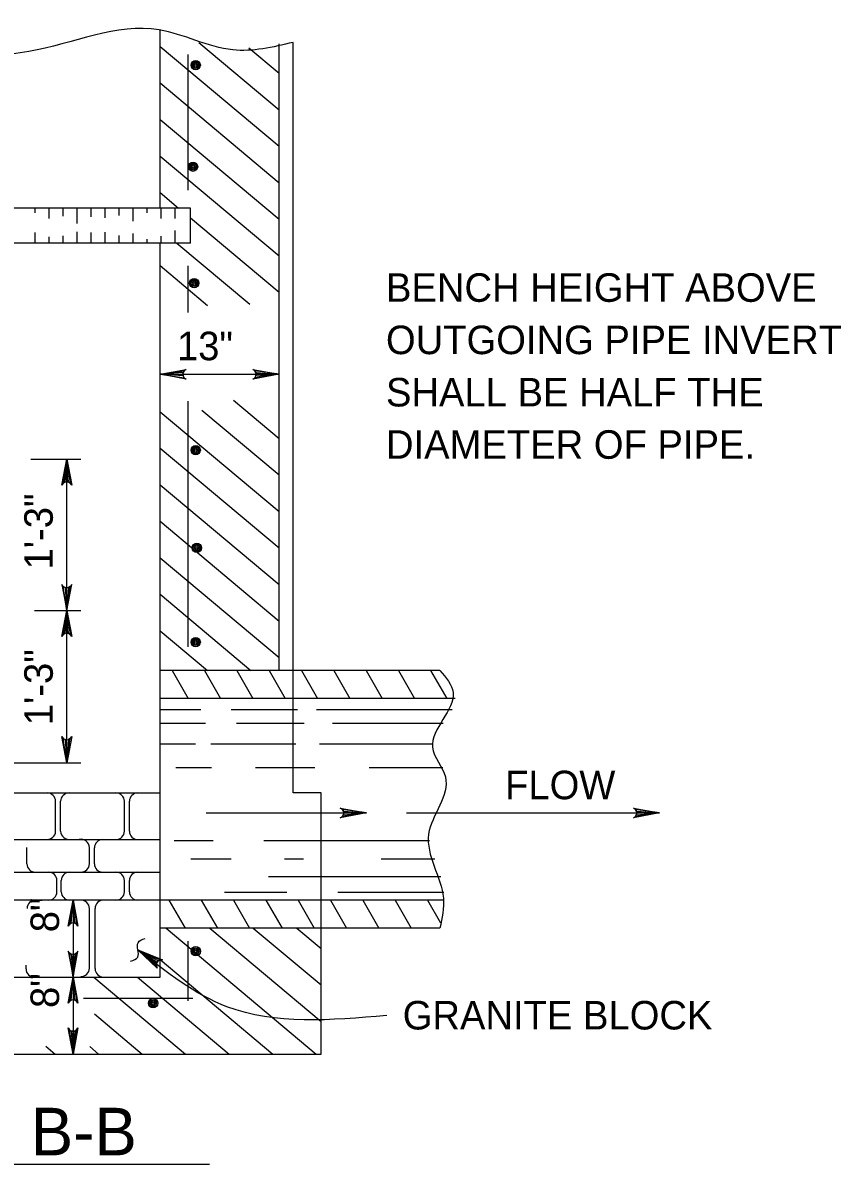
# Model space of a CAD drawing. Extents: x 0.2 to 7.1, y 1.2 to 11.2.
# Drawn here: x 2.099 to 3.819, y 3.123 to 5.523 of the extents above; entities that cross this region are included whole.
import ezdxf

# ---------------------------------------------------------------- set-up
doc = ezdxf.new("R2010")
doc.units = 0
for name, color, linetype in [('DETL-DIMS', 7, 'Continuous'), ('DETL-LINE', 7, 'Continuous'), ('DETL-NOTE', 7, 'Continuous'), ('DETL-PATT', 7, 'Continuous'), ('DETL-TITL', 7, 'Continuous')]:
    doc.layers.add(name, color=color, linetype=linetype)

msp = doc.modelspace()

# ---------------------------------------------------------------- linework, layer by layer
at = {"layer": 'DETL-DIMS'}
for p, q in [((2.3878, 4.7839), (2.6378, 4.7839)), ((2.1161, 4.6055), (2.2211, 4.6055)), ((2.1917, 3.9672), (2.1917, 4.6055)), ((2.1236, 4.2871), (2.2211, 4.2871)), ((2.0041, 3.9672), (2.2211, 3.9672)), ((2.4848, 3.8615), (2.8214, 3.8615)), ((2.9057, 3.8615), (3.4375, 3.8615)), ((2.2049, 3.6782), (2.2049, 3.3547))]:
    msp.add_line(p, q, dxfattribs=at)
for points in [[(2.3878, 4.7839), (2.4426, 4.7942), (2.4384, 4.7913), (2.4362, 4.7876), (2.4356, 4.7839), (2.4362, 4.7803), (2.4384, 4.7766), (2.4426, 4.7737), (2.3878, 4.7839), (2.4384, 4.7766), (2.4362, 4.7803), (2.3878, 4.7839), (2.4356, 4.7839), (2.4362, 4.7876), (2.3878, 4.7839), (2.4384, 4.7913)], [(2.6378, 4.7839), (2.5829, 4.7737), (2.5872, 4.7766), (2.5893, 4.7803), (2.59, 4.7839), (2.5893, 4.7876), (2.5872, 4.7913), (2.5829, 4.7942), (2.6378, 4.7839), (2.5872, 4.7913), (2.5893, 4.7876), (2.6378, 4.7839), (2.59, 4.7839), (2.5893, 4.7803), (2.6378, 4.7839), (2.5872, 4.7766)], [(2.1917, 4.6055), (2.202, 4.5506), (2.199, 4.5549), (2.1954, 4.557), (2.1917, 4.5577), (2.188, 4.557), (2.1843, 4.5549), (2.1814, 4.5506), (2.1917, 4.6055), (2.1843, 4.5549), (2.188, 4.557), (2.1917, 4.6055), (2.1917, 4.5577), (2.1954, 4.557), (2.1917, 4.6055), (2.199, 4.5549)], [(2.1917, 4.2871), (2.202, 4.3419), (2.199, 4.3377), (2.1954, 4.3355), (2.1917, 4.3349), (2.188, 4.3355), (2.1843, 4.3377), (2.1814, 4.3419), (2.1917, 4.2871), (2.1843, 4.3377), (2.188, 4.3355), (2.1917, 4.2871), (2.1917, 4.3349), (2.1954, 4.3355), (2.1917, 4.2871), (2.199, 4.3377)], [(2.1917, 4.2871), (2.202, 4.2323), (2.199, 4.2365), (2.1954, 4.2387), (2.1917, 4.2393), (2.188, 4.2387), (2.1843, 4.2365), (2.1814, 4.2323), (2.1917, 4.2871), (2.1843, 4.2365), (2.188, 4.2387), (2.1917, 4.2871), (2.1917, 4.2393), (2.1954, 4.2387), (2.1917, 4.2871), (2.199, 4.2365)], [(2.1917, 3.9672), (2.1814, 4.0221), (2.1843, 4.0178), (2.188, 4.0157), (2.1917, 4.015), (2.1954, 4.0157), (2.199, 4.0178), (2.202, 4.0221), (2.1917, 3.9672), (2.199, 4.0178), (2.1954, 4.0157), (2.1917, 3.9672), (2.1917, 4.015), (2.188, 4.0157), (2.1917, 3.9672), (2.1843, 4.0178)], [(2.8214, 3.8615), (2.7665, 3.8513), (2.7708, 3.8542), (2.7729, 3.8579), (2.7736, 3.8615), (2.7729, 3.8652), (2.7708, 3.8689), (2.7665, 3.8718), (2.8214, 3.8615), (2.7708, 3.8689), (2.7729, 3.8652), (2.8214, 3.8615), (2.7736, 3.8615), (2.7729, 3.8579), (2.8214, 3.8615), (2.7708, 3.8542)], [(3.4375, 3.8615), (3.3827, 3.8513), (3.3869, 3.8542), (3.3891, 3.8579), (3.3897, 3.8615), (3.3891, 3.8652), (3.3869, 3.8689), (3.3827, 3.8718), (3.4375, 3.8615), (3.3869, 3.8689), (3.3891, 3.8652), (3.4375, 3.8615), (3.3897, 3.8615), (3.3891, 3.8579), (3.4375, 3.8615), (3.3869, 3.8542)], [(2.2049, 3.6782), (2.2152, 3.6234), (2.2123, 3.6276), (2.2086, 3.6298), (2.2049, 3.6304), (2.2012, 3.6298), (2.1976, 3.6276), (2.1946, 3.6234), (2.2049, 3.6782), (2.1976, 3.6276), (2.2012, 3.6298), (2.2049, 3.6782), (2.2049, 3.6304), (2.2086, 3.6298), (2.2049, 3.6782), (2.2123, 3.6276)], [(2.2049, 3.5165), (2.2152, 3.5713), (2.2123, 3.5671), (2.2086, 3.5649), (2.2049, 3.5643), (2.2012, 3.5649), (2.1976, 3.5671), (2.1946, 3.5713), (2.2049, 3.5165), (2.1976, 3.5671), (2.2012, 3.5649), (2.2049, 3.5165), (2.2049, 3.5643), (2.2086, 3.5649), (2.2049, 3.5165), (2.2123, 3.5671)], [(2.3412, 3.5735), (2.3929, 3.5527), (2.3878, 3.5525), (2.384, 3.5505), (2.3815, 3.5478), (2.38, 3.5443), (2.3799, 3.5401), (2.3819, 3.5353), (2.3412, 3.5735), (2.3799, 3.5401), (2.38, 3.5443), (2.3412, 3.5735), (2.3815, 3.5478), (2.384, 3.5505), (2.3412, 3.5735), (2.3878, 3.5525)], [(2.2049, 3.5165), (2.2152, 3.4616), (2.2123, 3.4659), (2.2086, 3.468), (2.2049, 3.4687), (2.2012, 3.468), (2.1976, 3.4659), (2.1946, 3.4616), (2.2049, 3.5165), (2.1976, 3.4659), (2.2012, 3.468), (2.2049, 3.5165), (2.2049, 3.4687), (2.2086, 3.468), (2.2049, 3.5165), (2.2123, 3.4659)], [(2.2049, 3.3547), (2.1946, 3.4095), (2.1976, 3.4053), (2.2012, 3.4031), (2.2049, 3.4025), (2.2086, 3.4031), (2.2123, 3.4053), (2.2152, 3.4095), (2.2049, 3.3547), (2.2123, 3.4053), (2.2086, 3.4031), (2.2049, 3.3547), (2.2049, 3.4025), (2.2012, 3.4031), (2.2049, 3.3547), (2.1976, 3.4053)]]:
    msp.add_lwpolyline(points, dxfattribs=at)
for points in [[(2.3253, 3.5496), (2.341, 3.5585), (2.3414, 3.5887), (2.3562, 3.5978)], [(2.864, 3.4358), (2.5283, 3.4541), (2.3412, 3.5735)]]:
    msp.add_spline(points, degree=3, dxfattribs=at)
at = {"layer": 'DETL-LINE'}
for p, q in [((2.3878, 5.1333), (2.3878, 5.5079)), ((2.6378, 4.1611), (2.6378, 5.4784)), ((2.6672, 4.1611), (2.6672, 5.4817)), ((2.4466, 5.1708), (2.4466, 5.4563)), ((2.4515, 5.1333), (1.9564, 5.1333)), ((2.4515, 5.0598), (2.4515, 5.1333)), ((2.4515, 5.0598), (1.9564, 5.0598)), ((2.3878, 3.5165), (2.3878, 5.0598)), ((2.4466, 4.9135), (2.4466, 5.0116)), ((2.4466, 4.211), (2.4466, 4.7274)), ((2.976, 4.1611), (2.3878, 4.1611)), ((2.6672, 3.9037), (2.6672, 4.1611)), ((3.0077, 4.1022), (2.3878, 4.1022)), ((1.525, 3.9037), (2.3878, 3.9037)), ((2.726, 3.9037), (2.6672, 3.9037)), ((2.726, 3.6194), (2.726, 3.9037)), ((2.1682, 3.8233), (2.1682, 3.8861)), ((2.1787, 3.8233), (2.1787, 3.8861)), ((2.3128, 3.8233), (2.3128, 3.8861)), ((2.3233, 3.8233), (2.3233, 3.8861)), ((1.8815, 3.8057), (2.3548, 3.8057)), ((2.2763, 3.8057), (2.2835, 3.8057)), ((2.3482, 3.8057), (2.3878, 3.8057)), ((2.1078, 3.7547), (2.1078, 3.7888)), ((2.2392, 3.7547), (2.2392, 3.7888)), ((2.2497, 3.7547), (2.2497, 3.788)), ((1.8836, 3.7371), (2.3878, 3.7371)), ((2.1325, 3.7371), (2.1397, 3.7371)), ((2.2044, 3.7371), (2.2116, 3.7371)), ((2.2763, 3.7371), (2.2835, 3.7371)), ((2.3482, 3.7371), (2.3878, 3.7371)), ((2.1709, 3.6959), (2.1709, 3.7194)), ((2.1801, 3.6959), (2.1801, 3.7194)), ((2.3128, 3.6959), (2.3128, 3.7194)), ((2.3233, 3.6959), (2.3233, 3.7194)), ((2.3878, 3.6782), (1.8857, 3.6782)), ((2.1325, 3.6782), (2.1397, 3.6782)), ((2.9828, 3.6782), (2.3878, 3.6782)), ((2.2392, 3.5351), (2.2392, 3.6606)), ((2.251, 3.5342), (2.251, 3.6606)), ((2.976, 3.6194), (2.3878, 3.6194)), ((2.726, 3.3547), (2.726, 3.6194)), ((2.4466, 3.4662), (2.4466, 3.5922)), ((2.106, 3.534), (2.106, 3.5416)), ((1.525, 3.5165), (2.3878, 3.5165)), ((2.2269, 3.4723), (2.4563, 3.4723)), ((1.1868, 3.3547), (2.726, 3.3547))]:
    msp.add_line(p, q, dxfattribs=at)
for centre, radius in [((2.4626, 5.434), 0.0098), ((2.4626, 5.434), 0.00735), ((2.4626, 5.434), 0.0049), ((2.4626, 5.434), 0.00245), ((2.457, 5.2203), 0.0098), ((2.457, 5.2203), 0.00735), ((2.457, 5.2203), 0.0049), ((2.457, 5.2203), 0.00245), ((2.4594, 4.9757), 0.0098), ((2.4594, 4.9757), 0.00735), ((2.4594, 4.9757), 0.0049), ((2.4594, 4.9757), 0.00245), ((2.4626, 4.6244), 0.0098), ((2.4626, 4.6244), 0.00735), ((2.4626, 4.6244), 0.0049), ((2.4626, 4.6244), 0.00245), ((2.465, 4.4189), 0.0098), ((2.465, 4.4189), 0.00735), ((2.465, 4.4189), 0.0049), ((2.465, 4.4189), 0.00245), ((2.4626, 4.2209), 0.0098), ((2.4626, 4.2209), 0.00735), ((2.4626, 4.2209), 0.0049), ((2.4626, 4.2209), 0.00245), ((2.4627, 3.5708), 0.0098), ((2.4627, 3.5708), 0.00735), ((2.4627, 3.5708), 0.0049), ((2.4627, 3.5708), 0.00245), ((2.3731, 3.4614), 0.0098), ((2.3731, 3.4614), 0.00735), ((2.3731, 3.4614), 0.0049), ((2.3731, 3.4614), 0.00245)]:
    msp.add_circle(centre, radius, dxfattribs=at)
for centre, start, end in [((2.1506, 3.8861), 0, 90), ((2.1964, 3.8861), 90, 180), ((2.2951, 3.8861), 0, 90), ((2.3409, 3.8861), 90, 180), ((2.1506, 3.8233), 258.2538, 0), ((2.1964, 3.8233), 180, 281.7563), ((2.2951, 3.8233), 270, 0), ((2.3409, 3.8233), 180, 270), ((2.2215, 3.7888), 0, 101.7563), ((2.2673, 3.788), 90, 180), ((2.1255, 3.7547), 180, 270), ((2.2215, 3.7547), 270, 0), ((2.2673, 3.7547), 180, 270), ((2.1532, 3.7194), 0, 90), ((2.1977, 3.7194), 90, 180), ((2.2951, 3.7194), 0, 90), ((2.3409, 3.7194), 90, 180), ((2.1532, 3.6959), 270, 0), ((2.1977, 3.6959), 180, 270), ((2.2951, 3.6959), 270, 0), ((2.3409, 3.6959), 180, 270), ((2.126, 3.6606), 90, 180), ((2.2215, 3.6606), 0, 90), ((2.2687, 3.6606), 90, 180), ((2.1236, 3.534), 180, 270), ((2.2215, 3.5351), 270, 0), ((2.2687, 3.5342), 180, 270)]:
    msp.add_arc(centre, 0.0176, start, end, dxfattribs=at)
for points in [[(2.6672, 5.4817), (2.5405, 5.4658), (2.386, 5.508), (2.112, 5.4623), (1.5326, 5.5185), (1.2456, 5.4817)], [(2.976, 4.1611), (3.0036, 4.115), (2.9603, 3.9997), (2.9874, 3.9373), (2.9521, 3.8167), (2.9833, 3.6825), (2.976, 3.6194)]]:
    msp.add_spline(points, degree=3, dxfattribs=at)
at = {"layer": 'DETL-PATT'}
for p, q in [((2.3878, 5.4731), (2.6378, 5.2633)), ((2.4694, 5.4814), (2.6378, 5.3401)), ((2.5744, 5.4701), (2.6378, 5.4169)), ((2.3878, 5.3963), (2.6378, 5.1866)), ((2.3878, 5.3195), (2.6378, 5.1098)), ((2.3878, 5.2428), (2.6378, 5.033)), ((2.3878, 5.166), (2.4267, 5.1333)), ((2.1247, 5.1333), (2.1247, 5.1233)), ((2.1541, 5.1333), (2.1541, 5.1117)), ((2.1835, 5.1333), (2.1835, 5.1166)), ((2.2129, 5.1333), (2.2129, 5.1011)), ((2.2424, 5.1333), (2.2424, 5.1146)), ((2.2718, 5.1333), (2.2718, 5.1127)), ((2.3012, 5.1333), (2.3012, 5.1175)), ((2.3306, 5.1333), (2.3306, 5.1059)), ((2.36, 5.1333), (2.36, 5.1233)), ((2.3894, 5.1333), (2.3894, 5.1117)), ((2.4188, 5.1333), (2.4188, 5.1117)), ((2.4515, 5.1125), (2.6378, 4.9562)), ((2.1247, 5.0817), (2.1247, 5.0598)), ((2.1541, 5.073), (2.1541, 5.0598)), ((2.1835, 5.0749), (2.1835, 5.0598)), ((2.2129, 5.0836), (2.2129, 5.0598)), ((2.2424, 5.0817), (2.2424, 5.0598)), ((2.2718, 5.0827), (2.2718, 5.0598)), ((2.3012, 5.0759), (2.3012, 5.0598)), ((2.3306, 5.0798), (2.3306, 5.0598)), ((2.36, 5.0681), (2.36, 5.0598)), ((2.3894, 5.074), (2.3894, 5.0598)), ((2.4188, 5.0865), (2.4188, 5.0598)), ((2.4228, 5.0598), (2.5763, 4.931)), ((2.3878, 5.0124), (2.4874, 4.9288)), ((2.5418, 4.7296), (2.6378, 4.649)), ((2.3878, 4.7052), (2.6378, 4.4955)), ((2.4753, 4.7085), (2.6378, 4.5722)), ((2.3878, 4.6284), (2.6378, 4.4187)), ((2.3878, 4.5517), (2.6378, 4.3419)), ((2.3878, 4.4749), (2.6378, 4.2651)), ((2.3878, 4.3981), (2.6378, 4.1883)), ((2.3878, 4.3213), (2.5787, 4.1611)), ((2.3878, 4.2445), (2.4872, 4.1611)), ((2.413, 4.1611), (2.447, 4.1022)), ((2.4809, 4.1611), (2.5149, 4.1022)), ((2.5489, 4.1611), (2.5828, 4.1022)), ((2.6168, 4.1611), (2.6507, 4.1022)), ((2.6847, 4.1611), (2.7187, 4.1022)), ((2.7526, 4.1611), (2.7866, 4.1022)), ((2.8206, 4.1611), (2.8545, 4.1022)), ((2.8885, 4.1611), (2.9224, 4.1022)), ((2.9564, 4.1611), (2.9904, 4.1022)), ((2.4734, 4.0781), (2.3878, 4.0781)), ((2.6765, 4.0781), (2.5373, 4.0781)), ((3.0013, 4.0781), (2.7165, 4.0781)), ((2.483, 4.0493), (2.3878, 4.0493)), ((2.6909, 4.0493), (2.5485, 4.0493)), ((2.9824, 4.0493), (2.7501, 4.0493)), ((2.4622, 4.0061), (2.3878, 4.0061)), ((2.6733, 4.0061), (2.4942, 4.0061)), ((2.9604, 4.0061), (2.7229, 4.0061)), ((2.4958, 3.9565), (2.4206, 3.9565)), ((2.7133, 3.9565), (2.5885, 3.9565)), ((2.9818, 3.9565), (2.8269, 3.9565)), ((2.499, 3.8028), (2.4174, 3.8028)), ((2.9539, 3.8028), (2.6061, 3.8028)), ((2.5373, 3.7644), (2.4526, 3.7644)), ((2.6893, 3.7644), (2.6493, 3.7644)), ((2.9654, 3.7644), (2.8525, 3.7644)), ((2.9781, 3.7276), (2.6157, 3.7276)), ((2.4062, 3.6782), (2.4402, 3.6194)), ((2.4741, 3.6782), (2.5081, 3.6194)), ((2.6541, 3.694), (2.523, 3.694)), ((2.5421, 3.6782), (2.576, 3.6194)), ((2.61, 3.6782), (2.644, 3.6194)), ((2.6779, 3.6782), (2.7119, 3.6194)), ((2.7458, 3.6782), (2.7798, 3.6194)), ((2.9838, 3.694), (2.7613, 3.694)), ((2.8138, 3.6782), (2.8477, 3.6194)), ((2.8817, 3.6782), (2.9157, 3.6194)), ((2.9496, 3.6782), (2.9773, 3.6303)), ((2.4006, 3.6194), (2.7161, 3.3547)), ((2.4921, 3.6194), (2.726, 3.4232)), ((2.5837, 3.6194), (2.726, 3.5)), ((2.6752, 3.6194), (2.726, 3.5767)), ((2.3878, 3.5534), (2.6246, 3.3547)), ((2.2488, 3.5165), (2.4415, 3.3547)), ((2.3403, 3.5165), (2.5331, 3.3547)), ((2.2497, 3.4389), (2.35, 3.3547)), ((2.1478, 3.3709), (2.167, 3.3547)), ((2.2398, 3.3704), (2.2585, 3.3547))]:
    msp.add_line(p, q, dxfattribs=at)
at = {"layer": 'DETL-TITL'}
msp.add_line((1.4821, 3.1231), (2.4917, 3.1231), dxfattribs=at)

# ---------------------------------------------------------------- texts
at = {"layer": 'DETL-NOTE'}
for s, p in [('BENCH HEIGHT ABOVE', (2.8625, 4.9362)), ('13"', (2.4232, 4.8134)), ('OUTGOING PIPE INVERT', (2.8625, 4.8262)), ('SHALL BE HALF THE ', (2.8625, 4.7162)), ('DIAMETER OF PIPE.', (2.8625, 4.6062)), ('FLOW', (3.1128, 3.8904)), ('GRANITE BLOCK', (2.8977, 3.4063))]:
    msp.add_text(s, height=0.06, dxfattribs=at).set_placement(p)
for s, p in [('1\'-3"', (2.1623, 4.3735)), ('1\'-3"', (2.1623, 4.0461)), ('8"', (2.1755, 3.6107)), ('8"', (2.1755, 3.4515))]:
    msp.add_text(s, height=0.06, rotation=90, dxfattribs=at).set_placement(p)
at = {"layer": 'DETL-TITL'}
msp.add_text('SECTION B-B', height=0.1, dxfattribs=at).set_placement((1.4845, 3.1417))

doc.saveas('drawing.dxf')
